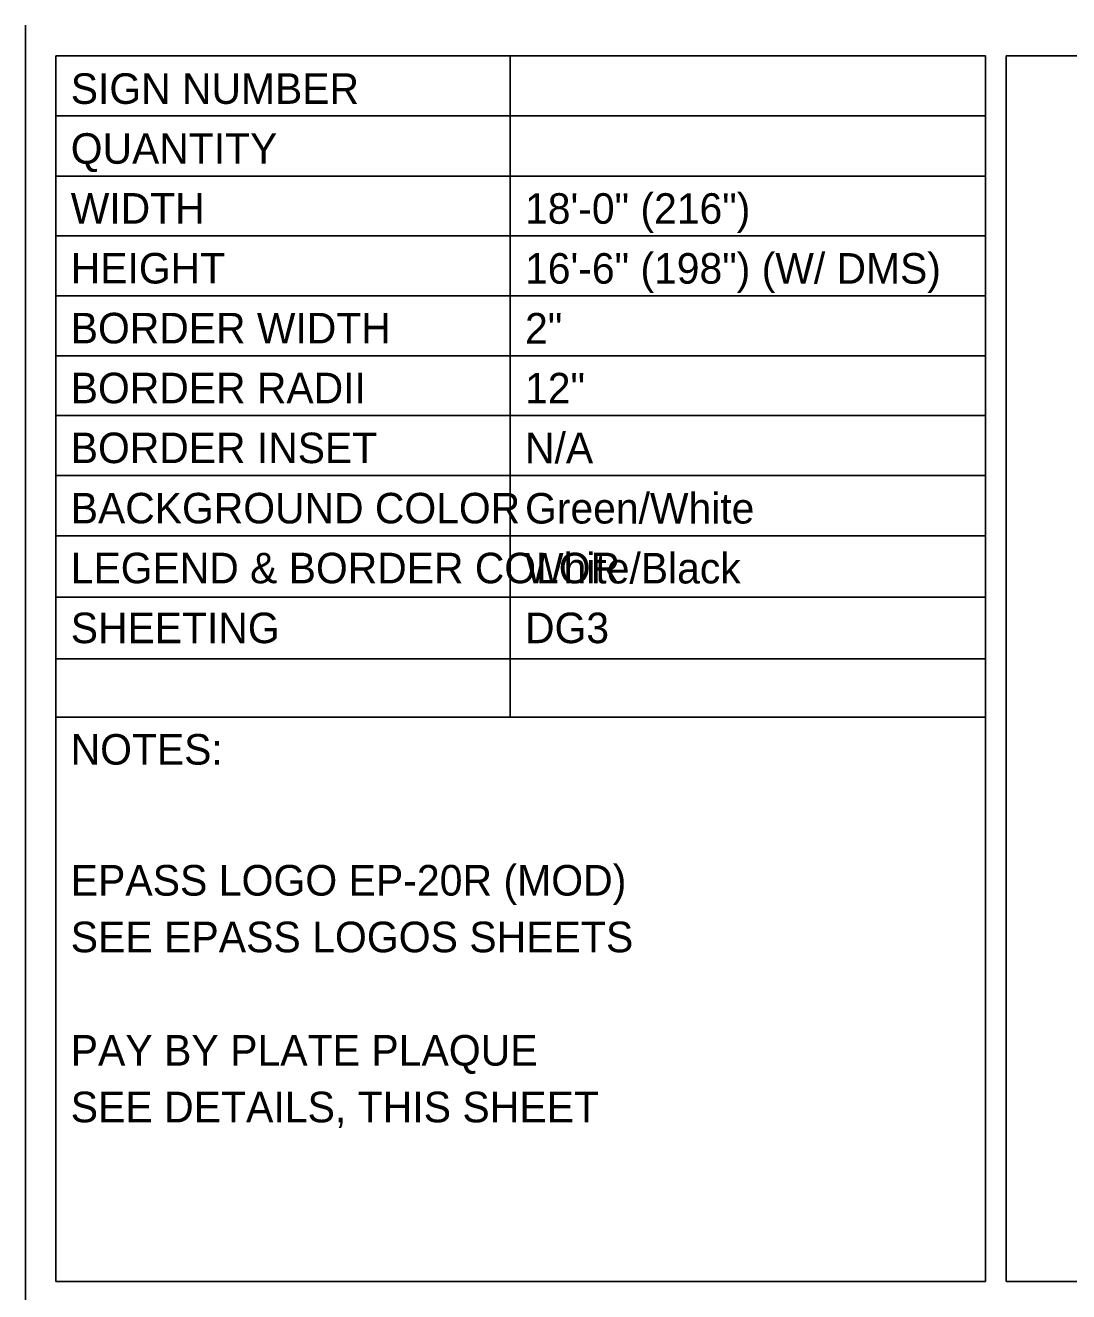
# Model space of a CAD drawing. Extents: x 10268312 to 10268706, y 2142548 to 2142786.
# Drawn here: x 10268394.73 to 10268420.26, y 2142657.28 to 2142688.28 of the extents above; entities that cross this region are included whole.
import ezdxf

# ---------------------------------------------------------------- set-up
doc = ezdxf.new("R2010")
doc.units = 0
for name, color, linetype in [('SheetBorder_dp', 7, 'Continuous'), ('SumBoxLines_dp', 7, 'Continuous'), ('TextMisc', 7, 'Continuous')]:
    doc.layers.add(name, color=color, linetype=linetype)

msp = doc.modelspace()

# ---------------------------------------------------------------- linework, layer by layer
at = {"layer": 'SheetBorder_dp'}
msp.add_line((10268394.73, 2142688.282), (10268394.73, 2142592.282), dxfattribs=at)
at = {"layer": 'SumBoxLines_dp'}
for p, q in [((10268395.48, 2142687.532), (10268395.48, 2142657.532)), ((10268395.48, 2142687.532), (10268418.23, 2142687.532)), ((10268406.598, 2142687.528), (10268406.598, 2142671.345)), ((10268418.23, 2142687.532), (10268418.23, 2142657.532)), ((10268418.73, 2142687.532), (10268418.73, 2142657.532)), ((10268418.73, 2142687.532), (10268470.98, 2142687.532)), ((10268395.48, 2142686.066), (10268418.23, 2142686.066)), ((10268395.48, 2142684.59), (10268418.23, 2142684.59)), ((10268395.48, 2142683.125), (10268418.23, 2142683.125)), ((10268395.48, 2142681.659), (10268418.23, 2142681.659)), ((10268395.48, 2142680.193), (10268418.23, 2142680.193)), ((10268395.48, 2142678.727), (10268418.23, 2142678.727)), ((10268395.48, 2142677.261), (10268418.23, 2142677.261)), ((10268395.48, 2142675.786), (10268418.23, 2142675.786)), ((10268395.48, 2142674.281), (10268418.23, 2142674.281)), ((10268395.48, 2142672.776), (10268418.23, 2142672.776)), ((10268395.478, 2142671.345), (10268418.229, 2142671.345)), ((10268395.48, 2142657.532), (10268418.23, 2142657.532)), ((10268418.73, 2142657.532), (10268470.98, 2142657.532))]:
    msp.add_line(p, q, dxfattribs=at)

# ---------------------------------------------------------------- texts
at = {"layer": 'TextMisc'}
for s, height, p in [('SIGN NUMBER', 0.74756, (10268395.842, 2142686.359)), ('QUANTITY', 0.7476, (10268395.842, 2142684.893)), ('WIDTH', 0.7476, (10268395.842, 2142683.427)), ('18\'-0" (216")', 0.74756, (10268406.959, 2142683.424)), ('HEIGHT', 0.7476, (10268395.842, 2142681.962)), ('16\'-6" (198") (W/ DMS)', 0.74756, (10268406.959, 2142681.958)), ('BORDER WIDTH', 0.74756, (10268395.842, 2142680.496)), ('2"', 0.7476, (10268406.959, 2142680.492)), ('BORDER RADII', 0.74756, (10268395.842, 2142679.03)), ('12"', 0.7476, (10268406.959, 2142679.026)), ('BORDER INSET', 0.74756, (10268395.842, 2142677.564)), ('N/A', 0.7476, (10268406.959, 2142677.561)), ('Green/White', 0.74756, (10268406.959, 2142676.085)), ('BACKGROUND COLOR', 0.74756, (10268395.842, 2142676.089)), ('LEGEND & BORDER COLOR', 0.74756, (10268395.842, 2142674.623)), ('White/Black', 0.74756, (10268406.959, 2142674.619)), ('SHEETING', 0.7476, (10268395.842, 2142673.157)), ('DG3', 0.7476, (10268406.959, 2142673.157)), ('NOTES:', 0.7476, (10268395.84, 2142670.184)), ('EPASS LOGO EP-20R (MOD)', 0.75, (10268395.84, 2142666.977)), ('SEE EPASS LOGOS SHEETS', 0.75, (10268395.84, 2142665.59)), ('PAY BY PLATE PLAQUE', 0.75, (10268395.84, 2142662.815)), ('SEE DETAILS, THIS SHEET', 0.75, (10268395.84, 2142661.427))]:
    msp.add_text(s, height=height, dxfattribs=at).set_placement(p)

doc.saveas('drawing.dxf')
